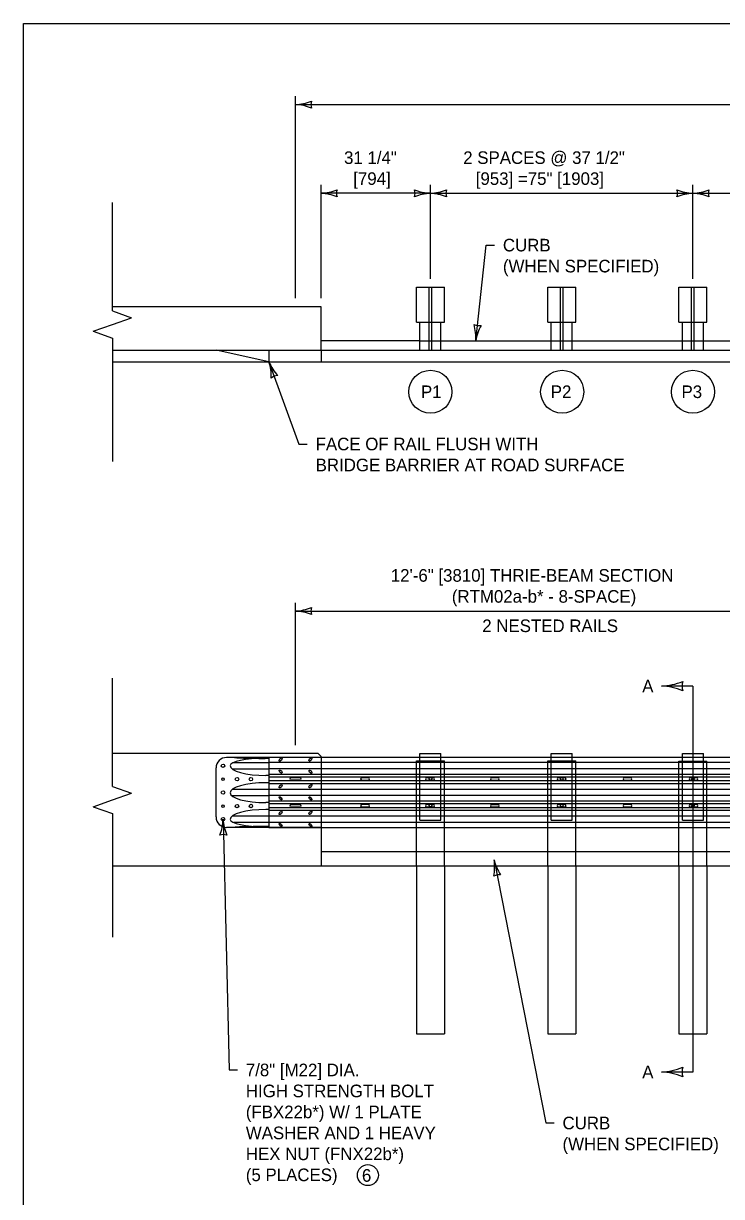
# Model space of a CAD drawing. Extents: x 49991 to 50160, y 49948 to 50051.
# Drawn here: x 49999.38 to 50002.71, y 49993.41 to 49999 of the extents above; entities that cross this region are included whole.
import ezdxf

# ---------------------------------------------------------------- set-up
doc = ezdxf.new("R2010")
doc.units = 0
for name, color, linetype in [('Level 1', 7, 'Continuous'), ('Level 2', 7, 'Continuous'), ('Level 3', 7, 'Continuous'), ('Level 4', 7, 'Continuous'), ('Level 6', 7, 'Continuous')]:
    doc.layers.add(name, color=color, linetype=linetype)

msp = doc.modelspace()

# ---------------------------------------------------------------- linework, layer by layer
at = {"layer": 'Level 1'}
for p, q in [((50001.255, 49997.5765), (50001.255, 49997.7432)), ((50001.255, 49997.7432), (50001.3883, 49997.7432)), ((50001.3883, 49997.5765), (50001.3883, 49997.7432)), ((50001.88, 49997.5765), (50001.88, 49997.7431)), ((50001.88, 49997.7431), (50002.0133, 49997.7431)), ((50002.0133, 49997.5765), (50002.0133, 49997.7431)), ((50002.505, 49997.5765), (50002.505, 49997.7431)), ((50002.505, 49997.7431), (50002.6383, 49997.7431)), ((50002.6383, 49997.5765), (50002.6383, 49997.7431)), ((50001.255, 49997.5765), (50001.3883, 49997.5765)), ((50001.2716, 49997.4432), (50001.2716, 49997.5765)), ((50001.2716, 49997.5765), (50001.3716, 49997.5765)), ((50001.3716, 49997.4432), (50001.3716, 49997.5765)), ((50001.88, 49997.5765), (50002.0133, 49997.5765)), ((50001.8966, 49997.4431), (50001.8966, 49997.5765)), ((50001.8966, 49997.5765), (50001.9966, 49997.5765)), ((50001.9966, 49997.4431), (50001.9966, 49997.5765)), ((50002.505, 49997.5765), (50002.6383, 49997.5765)), ((50002.5216, 49997.4431), (50002.5216, 49997.5765)), ((50002.5216, 49997.5765), (50002.6216, 49997.5765)), ((50002.6216, 49997.4431), (50002.6216, 49997.5765)), ((49999.8072, 49997.4432), (50011.6716, 49997.4427)), ((50000.5527, 49997.387), (50000.3008, 49997.4432)), ((50000.5527, 49997.4432), (50000.5527, 49997.387)), ((50001.2716, 49997.487), (50000.8008, 49997.487)), ((50001.2716, 49997.4432), (50001.3716, 49997.4432)), ((50001.3716, 49997.487), (50001.8966, 49997.4869)), ((50001.8966, 49997.4431), (50001.9966, 49997.4431)), ((50001.9966, 49997.4869), (50002.5216, 49997.4869)), ((50002.5216, 49997.4431), (50002.6216, 49997.4431)), ((50002.6216, 49997.4869), (50002.8341, 49997.4869)), ((49999.8072, 49997.387), (50011.6716, 49997.3865)), ((50000.7868, 49995.5206), (49999.8072, 49995.5206)), ((50000.8008, 49995.5019), (50000.3508, 49995.5019)), ((50000.5527, 49995.4977), (50000.5341, 49995.4977)), ((50004.3866, 49995.5019), (50000.5527, 49995.5019)), ((50000.5527, 49995.5019), (50000.5527, 49995.1685)), ((50000.7868, 49995.5206), (50000.8008, 49995.5066)), ((50000.8008, 49995.5019), (50000.8008, 49995.5066)), ((50001.2716, 49995.5206), (50001.3716, 49995.5206)), ((50001.2716, 49995.5019), (50001.2716, 49995.5206)), ((50001.3716, 49995.5019), (50001.3716, 49995.5206)), ((50001.8966, 49995.5206), (50001.9966, 49995.5206)), ((50001.8966, 49995.5018), (50001.8966, 49995.5206)), ((50001.9966, 49995.5018), (50001.9966, 49995.5206)), ((50002.5216, 49995.5206), (50002.6216, 49995.5206)), ((50002.5216, 49995.5018), (50002.5216, 49995.5206)), ((50002.6216, 49995.5018), (50002.6216, 49995.5206)), ((50000.3008, 49995.2188), (50000.3008, 49995.4519)), ((50000.5527, 49995.4763), (50000.3797, 49995.4763)), ((50000.5527, 49995.4456), (50000.38, 49995.4456)), ((50004.5497, 49995.4776), (50000.5527, 49995.4776)), ((50004.5497, 49995.4485), (50000.5527, 49995.4484)), ((50000.5527, 49995.4165), (50000.5383, 49995.4165)), ((50000.5527, 49995.3813), (50000.5383, 49995.3813)), ((50004.5497, 49995.4214), (50000.5527, 49995.4214)), ((50003.4109, 49995.4083), (50000.5527, 49995.4083)), ((50003.4095, 49995.3899), (50000.5527, 49995.3899)), ((50004.5499, 49995.3768), (50000.5527, 49995.3768)), ((50000.6998, 49995.4056), (50000.6581, 49995.4056)), ((50000.6998, 49995.4056), (50000.6581, 49995.4056)), ((50000.6998, 49995.4056), (50000.6581, 49995.4056)), ((50000.6998, 49995.4056), (50000.6581, 49995.4056)), ((50000.6998, 49995.4056), (50000.6581, 49995.4056)), ((50000.6998, 49995.3931), (50000.6581, 49995.3931)), ((50000.6998, 49995.3931), (50000.6581, 49995.3931)), ((50000.6998, 49995.3931), (50000.6581, 49995.3931)), ((50000.6998, 49995.3931), (50000.6581, 49995.3931)), ((50000.6998, 49995.3931), (50000.6581, 49995.3931)), ((50000.9957, 49995.406), (50001.0252, 49995.406)), ((50001.0252, 49995.3929), (50000.9957, 49995.3929)), ((50001.3046, 49995.406), (50001.3341, 49995.406)), ((50001.3341, 49995.3928), (50001.3046, 49995.3928)), ((50001.6134, 49995.4059), (50001.643, 49995.4059)), ((50001.643, 49995.3928), (50001.6134, 49995.3928)), ((50001.9311, 49995.406), (50001.9606, 49995.406)), ((50001.9606, 49995.3928), (50001.9311, 49995.3928)), ((50002.2453, 49995.406), (50002.2748, 49995.406)), ((50002.2748, 49995.3928), (50002.2453, 49995.3928)), ((50002.5595, 49995.406), (50002.589, 49995.406)), ((50002.589, 49995.3928), (50002.5595, 49995.3928)), ((50000.5527, 49995.3189), (50000.3766, 49995.3189)), ((50000.5527, 49995.3496), (50000.3768, 49995.3496)), ((50004.5505, 49995.3498), (50000.5527, 49995.3498)), ((50004.5497, 49995.3206), (50000.5527, 49995.3206)), ((50000.5527, 49995.2872), (50000.5383, 49995.2872)), ((50004.5497, 49995.2936), (50000.5527, 49995.2936)), ((50003.4116, 49995.2805), (50000.5527, 49995.2805)), ((50003.4083, 49995.2621), (50000.5527, 49995.2621)), ((50000.6998, 49995.2769), (50000.6581, 49995.2769)), ((50000.6998, 49995.2769), (50000.6581, 49995.2769)), ((50000.6998, 49995.2769), (50000.6581, 49995.2769)), ((50000.6998, 49995.2769), (50000.6581, 49995.2769)), ((50000.6998, 49995.2769), (50000.6581, 49995.2769)), ((50000.6998, 49995.2644), (50000.6581, 49995.2644)), ((50000.6998, 49995.2644), (50000.6581, 49995.2644)), ((50000.6998, 49995.2644), (50000.6581, 49995.2644)), ((50000.6998, 49995.2644), (50000.6581, 49995.2644)), ((50000.6998, 49995.2644), (50000.6581, 49995.2644)), ((50000.9957, 49995.2787), (50001.0252, 49995.2787)), ((50001.0252, 49995.2656), (50000.9957, 49995.2656)), ((50001.3046, 49995.2787), (50001.3341, 49995.2787)), ((50001.3341, 49995.2655), (50001.3046, 49995.2655)), ((50001.6134, 49995.2786), (50001.643, 49995.2786)), ((50001.643, 49995.2655), (50001.6134, 49995.2655)), ((50001.9311, 49995.2787), (50001.9606, 49995.2787)), ((50001.9606, 49995.2655), (50001.9311, 49995.2655)), ((50002.2453, 49995.2787), (50002.2748, 49995.2787)), ((50002.2748, 49995.2655), (50002.2453, 49995.2655)), ((50002.5595, 49995.2787), (50002.589, 49995.2787)), ((50002.589, 49995.2655), (50002.5595, 49995.2655)), ((50000.5527, 49995.2223), (50000.3767, 49995.2223)), ((50000.5527, 49995.2542), (50000.5383, 49995.2542)), ((50004.5497, 49995.249), (50000.5527, 49995.249)), ((50004.5497, 49995.222), (50000.5527, 49995.222)), ((50000.8008, 49995.1685), (50000.3508, 49995.1685)), ((50000.8008, 49995.1685), (50000.3508, 49995.1685)), ((50000.5527, 49995.1917), (50000.3851, 49995.1917)), ((50000.5527, 49995.1917), (50000.3851, 49995.1917)), ((50000.5527, 49995.1727), (50000.5341, 49995.1727)), ((50004.5497, 49995.1928), (50000.5527, 49995.1928)), ((50000.5527, 49995.1685), (50004.5497, 49995.1685)), ((50000.8008, 49995.1685), (50000.8008, 49994.9852)), ((50001.255, 49995.0519), (50001.255, 49995.1685)), ((50001.3883, 49995.0519), (50001.3883, 49995.1685)), ((50001.88, 49995.0518), (50001.88, 49995.1685)), ((50002.0133, 49995.0518), (50002.0133, 49995.1685)), ((50002.505, 49995.0518), (50002.505, 49995.1685)), ((50002.6383, 49995.0518), (50002.6383, 49995.1685)), ((50011.6716, 49995.0514), (50000.8008, 49995.0519)), ((49999.8072, 49994.9853), (50011.6716, 49994.9848))]:
    msp.add_line(p, q, dxfattribs=at)
msp.add_lwpolyline([(49999.3835, 49998.9992), (50016.7501, 49998.9992), (50016.7501, 49987.7988), (49999.3835, 49987.7988)], close=True, dxfattribs=at)
msp.add_lwpolyline([(50000.8008, 49997.4432), (50000.8008, 49997.6496), (49999.8072, 49997.6496)], dxfattribs=at)
for centre, radius in [((50000.3337, 49995.4625), 0.00833), ((50000.3337, 49995.3985), 0.00625), ((50000.4004, 49995.3985), 0.00833), ((50000.4004, 49995.3985), 0.00833), ((50000.4004, 49995.3985), 0.00833), ((50000.4004, 49995.3985), 0.00833), ((50000.4004, 49995.3985), 0.00833), ((50000.4666, 49995.3989), 0.00833), ((50000.4666, 49995.3989), 0.00833), ((50000.4666, 49995.3989), 0.00833), ((50000.4666, 49995.3989), 0.00833), ((50000.4666, 49995.3989), 0.00833), ((50001.3216, 49995.3998), 0.00625), ((50001.9466, 49995.3998), 0.00625), ((50002.5716, 49995.3997), 0.00625), ((50000.3337, 49995.3352), 0.00833), ((50000.3337, 49995.2703), 0.00625), ((50000.4004, 49995.2703), 0.00833), ((50000.4004, 49995.2703), 0.00833), ((50000.4004, 49995.2703), 0.00833), ((50000.4004, 49995.2703), 0.00833), ((50000.4004, 49995.2703), 0.00833), ((50000.4666, 49995.2707), 0.00833), ((50000.4666, 49995.2707), 0.00833), ((50000.4666, 49995.2707), 0.00833), ((50000.4666, 49995.2707), 0.00833), ((50000.4666, 49995.2707), 0.00833), ((50001.3216, 49995.2727), 0.00625), ((50001.9466, 49995.2727), 0.00625), ((50002.5716, 49995.2727), 0.00625), ((50000.3337, 49995.2079), 0.00833)]:
    msp.add_circle(centre, radius, dxfattribs=at)
for centre, radius, start, end in [((50000.3508, 49995.4519), 0.05, 90, 180), ((50000.6581, 49995.3993), 0.00625, 90, 270), ((50000.6581, 49995.3993), 0.00625, 90, 270), ((50000.6581, 49995.3993), 0.00625, 90, 270), ((50000.6581, 49995.3993), 0.00625, 90, 270), ((50000.6581, 49995.3993), 0.00625, 90, 270), ((50000.6998, 49995.3993), 0.00625, 270, 90), ((50000.6998, 49995.3993), 0.00625, 270, 90), ((50000.6998, 49995.3993), 0.00625, 270, 90), ((50000.6998, 49995.3993), 0.00625, 270, 90), ((50000.6998, 49995.3993), 0.00625, 270, 90), ((50000.9957, 49995.3994), 0.00656, 90, 270), ((50001.0252, 49995.3994), 0.00656, 270, 90), ((50001.3046, 49995.3994), 0.00656, 90, 270), ((50001.3341, 49995.3994), 0.00656, 270, 90), ((50001.6134, 49995.3994), 0.00656, 90, 270), ((50001.643, 49995.3994), 0.00656, 270, 90), ((50001.9311, 49995.3994), 0.00656, 90, 270), ((50001.9606, 49995.3994), 0.00656, 270, 90), ((50002.2453, 49995.3994), 0.00656, 90, 270), ((50002.2748, 49995.3994), 0.00656, 270, 90), ((50002.5595, 49995.3994), 0.00656, 90, 270), ((50002.589, 49995.3994), 0.00656, 270, 90), ((50000.6581, 49995.2707), 0.00625, 90, 270), ((50000.6581, 49995.2707), 0.00625, 90, 270), ((50000.6581, 49995.2707), 0.00625, 90, 270), ((50000.6581, 49995.2707), 0.00625, 90, 270), ((50000.6581, 49995.2707), 0.00625, 90, 270), ((50000.6998, 49995.2707), 0.00625, 270, 90), ((50000.6998, 49995.2707), 0.00625, 270, 90), ((50000.6998, 49995.2707), 0.00625, 270, 90), ((50000.6998, 49995.2707), 0.00625, 270, 90), ((50000.6998, 49995.2707), 0.00625, 270, 90), ((50000.9957, 49995.2721), 0.00656, 90, 270), ((50001.0252, 49995.2721), 0.00656, 270, 90), ((50001.3046, 49995.2721), 0.00656, 90, 270), ((50001.3341, 49995.2721), 0.00656, 270, 90), ((50001.6134, 49995.2721), 0.00656, 90, 270), ((50001.643, 49995.2721), 0.00656, 270, 90), ((50001.9311, 49995.2721), 0.00656, 90, 270), ((50001.9606, 49995.2721), 0.00656, 270, 90), ((50002.2453, 49995.2721), 0.00656, 90, 270), ((50002.2748, 49995.2721), 0.00656, 270, 90), ((50002.5595, 49995.2721), 0.00656, 90, 270), ((50002.589, 49995.2721), 0.00656, 270, 90), ((50000.3508, 49995.2185), 0.05, 180, 270)]:
    msp.add_arc(centre, radius, start, end, dxfattribs=at)
for centre, major_axis, ratio, start_param, end_param in [((50000.5341, 49995.4633), (-0.1667, 0), 0.2062, 4.712389, 6.283185), ((50000.5341, 49995.4633), (-0.1667, 0), 0.2062, 4.712389, 6.283185), ((50000.5341, 49995.4633), (-0.1667, 0), 0.2062, 4.712389, 6.283185), ((50000.5341, 49995.4633), (-0.1667, 0), 0.2062, 4.712389, 6.283185), ((50000.5341, 49995.4633), (-0.1667, 0), 0.2062, 4.712389, 6.283185), ((50000.5341, 49995.5019), (-0.1461, 0), 0.028516, 0, 1.570796), ((50000.5341, 49995.5019), (-0.1461, 0), 0.028516, 0, 1.570796), ((50000.5341, 49995.5019), (-0.1461, 0), 0.028516, 0, 1.570796), ((50000.5341, 49995.5019), (-0.1461, 0), 0.028516, 0, 1.570796), ((50000.5341, 49995.5019), (-0.1461, 0), 0.028516, 0, 1.570796), ((50000.5383, 49995.4633), (-0.1708, 0), 0.27561, 0, 1.570796), ((50000.5383, 49995.4633), (-0.1708, 0), 0.27561, 0, 1.570796), ((50000.5383, 49995.4633), (-0.1708, 0), 0.27561, 0, 1.570796), ((50000.5383, 49995.4633), (-0.1708, 0), 0.27561, 0, 1.570796), ((50000.5383, 49995.4633), (-0.1708, 0), 0.27561, 0, 1.570796), ((50000.5383, 49995.3342), (-0.1708, 0), 0.27561, 4.712389, 6.283185), ((50000.5383, 49995.3342), (-0.1708, 0), 0.27561, 4.712389, 6.283185), ((50000.5383, 49995.3342), (-0.1708, 0), 0.27561, 4.712389, 6.283185), ((50000.5383, 49995.3342), (-0.1708, 0), 0.27561, 4.712389, 6.283185), ((50000.5383, 49995.3342), (-0.1708, 0), 0.27561, 4.712389, 6.283185), ((50000.5383, 49995.3341), (-0.1708, 0), 0.27561, 0, 1.570796), ((50000.5383, 49995.3341), (-0.1708, 0), 0.27561, 0, 1.570796), ((50000.5383, 49995.3341), (-0.1708, 0), 0.27561, 0, 1.570796), ((50000.5383, 49995.3341), (-0.1708, 0), 0.27561, 0, 1.570796), ((50000.5383, 49995.3341), (-0.1708, 0), 0.27561, 0, 1.570796), ((50000.5383, 49995.2071), (-0.1708, 0), 0.27561, 4.712389, 6.283185), ((50000.5383, 49995.2071), (-0.1708, 0), 0.27561, 4.712389, 6.283185), ((50000.5383, 49995.2071), (-0.1708, 0), 0.27561, 4.712389, 6.283185), ((50000.5383, 49995.2071), (-0.1708, 0), 0.27561, 4.712389, 6.283185), ((50000.5383, 49995.2071), (-0.1708, 0), 0.27561, 4.712389, 6.283185), ((50000.5341, 49995.2071), (-0.1667, 0), 0.2062, 0, 1.570796), ((50000.5341, 49995.2071), (-0.1667, 0), 0.2062, 0, 1.570796), ((50000.5341, 49995.2071), (-0.1667, 0), 0.2062, 0, 1.570796), ((50000.5341, 49995.2071), (-0.1667, 0), 0.2062, 0, 1.570796), ((50000.5341, 49995.2071), (-0.1667, 0), 0.2062, 0, 1.570796), ((50000.5341, 49995.1685), (-0.1461, 0), 0.028516, 4.712389, 6.283185), ((50000.5341, 49995.1685), (-0.1461, 0), 0.028516, 4.712389, 6.283185), ((50000.5341, 49995.1685), (-0.1461, 0), 0.028516, 4.712389, 6.283185), ((50000.5341, 49995.1685), (-0.1461, 0), 0.028516, 4.712389, 6.283185), ((50000.5341, 49995.1685), (-0.1461, 0), 0.028516, 4.712389, 6.283185)]:
    msp.add_ellipse(centre, major_axis=major_axis, ratio=ratio, start_param=start_param, end_param=end_param, dxfattribs=at)
for centre, major_axis in [((50000.6082, 49995.4922), (-0.00633, -0.00754)), ((50000.7497, 49995.4922), (-0.00633, -0.00754)), ((50000.6082, 49995.4347), (-0.00633, 0.00754)), ((50000.7497, 49995.4347), (-0.00633, 0.00754)), ((50000.6082, 49995.3649), (-0.00633, -0.00754)), ((50000.7497, 49995.3649), (-0.00633, -0.00754)), ((50000.6082, 49995.3074), (-0.00633, 0.00754)), ((50000.7497, 49995.3074), (-0.00633, 0.00754)), ((50000.6082, 49995.2378), (-0.00633, -0.00754)), ((50000.7497, 49995.2378), (-0.00633, -0.00754)), ((50000.6082, 49995.1803), (-0.00633, 0.00754)), ((50000.7497, 49995.1803), (-0.00633, 0.00754))]:
    msp.add_ellipse(centre, major_axis=major_axis, ratio=0.447911, dxfattribs=at)
at = {"layer": 'Level 2'}
for centre, radius in [((50001.3215, 49997.2443), 0.1026), ((50001.949, 49997.2443), 0.1026), ((50002.5716, 49997.2443), 0.1026), ((50001.0235, 49993.512), 0.05)]:
    msp.add_circle(centre, radius, dxfattribs=at)
at = {"layer": 'Level 3'}
for p, q in [((50000.679, 49997.6896), (50000.679, 49998.6527)), ((50000.679, 49998.6127), (50008.1966, 49998.6127)), ((50000.8008, 49997.6896), (50000.8008, 49998.2299)), ((50001.3216, 49997.7832), (50001.3216, 49998.2299)), ((50002.5716, 49997.7831), (50002.5716, 49998.2299)), ((50001.3216, 49998.1899), (50000.8008, 49998.1899)), ((50001.3216, 49998.1899), (50002.5716, 49998.1899)), ((50002.5716, 49998.1899), (50003.8216, 49998.1899)), ((50001.5376, 49997.487), (50001.5866, 49997.9431)), ((50001.5866, 49997.9431), (50001.6266, 49997.9431)), ((50000.5527, 49997.387), (50000.6949, 49996.9955)), ((50000.6949, 49996.9955), (50000.7349, 49996.9955)), ((50000.679, 49995.5606), (50000.679, 49996.2394)), ((50000.679, 49996.1994), (50003.1966, 49996.1994)), ((50000.3337, 49995.2079), (50000.3624, 49994.0131)), ((50001.6247, 49995.0141), (50001.8705, 49993.7604)), ((50000.3624, 49994.0131), (50000.4024, 49994.0131)), ((50001.8705, 49993.7604), (50001.9105, 49993.7604))]:
    msp.add_line(p, q, dxfattribs=at)
for centre, radius, start, end in [((50000.6675, 49998.8454), 0.233, 272.8273, 292.0772), ((50000.8072, 49998.6127), 0.0548, 162.1388, 197.8612), ((50000.6699, 49998.3905), 0.2223, 67.456, 87.6395), ((50000.7893, 49998.4226), 0.233, 272.8273, 292.0772), ((50000.7917, 49997.9678), 0.2223, 67.456, 87.6395), ((50000.929, 49998.1899), 0.0548, 162.1388, 197.8612), ((50001.3308, 49998.412), 0.2223, 247.456, 267.6395), ((50001.1934, 49998.1899), 0.0548, 342.1388, 17.8612), ((50001.3331, 49997.9572), 0.233, 92.8273, 112.0772), ((50001.3102, 49998.4226), 0.233, 272.8273, 292.0772), ((50001.3125, 49997.9678), 0.2223, 67.456, 87.6395), ((50001.4499, 49998.1899), 0.0548, 162.1388, 197.8612), ((50002.5808, 49998.412), 0.2223, 247.456, 267.6395), ((50002.4434, 49998.1899), 0.0548, 342.1388, 17.8612), ((50002.5831, 49997.9572), 0.233, 92.8273, 112.0772), ((50002.5602, 49998.4226), 0.233, 272.8273, 292.0772), ((50002.5625, 49997.9678), 0.2223, 67.456, 87.6395), ((50002.6999, 49998.1899), 0.0548, 162.1388, 197.8612), ((50001.5513, 49997.6144), 0.0548, 246.0178, 281.7402), ((50001.305, 49997.5003), 0.233, 356.7063, 15.9562), ((50001.7575, 49997.4542), 0.2223, 151.335, 171.5185), ((50000.3408, 49997.3197), 0.2223, 357.4214, 17.6049), ((50000.7675, 49997.4772), 0.233, 202.7927, 222.0426), ((50000.5965, 49997.2665), 0.0548, 92.1042, 127.8266), ((50000.6675, 49996.4322), 0.233, 272.8273, 292.0772), ((50000.8072, 49996.1994), 0.0548, 162.1388, 197.8612), ((50000.6698, 49995.9773), 0.2223, 67.456, 87.6395), ((50002.4063, 49996.1523), 0.3107, 272.8273, 292.0772), ((50002.4094, 49995.5459), 0.2964, 67.456, 87.6395), ((50002.5926, 49995.842), 0.073, 162.1388, 197.8612), ((50000.1114, 49995.2117), 0.2223, 338.834, 359.0175), ((50000.5661, 49995.225), 0.233, 184.2053, 203.4551), ((50000.3368, 49995.0797), 0.0548, 73.5168, 109.2391), ((50001.4049, 49994.9803), 0.2223, 348.5492, 8.7327), ((50001.8508, 49995.0701), 0.233, 193.9205, 213.1704), ((50001.6494, 49994.8882), 0.0548, 83.232, 118.9544), ((50002.4063, 49994.3136), 0.3107, 272.8273, 292.0772), ((50002.4094, 49993.7071), 0.2964, 67.456, 87.6395), ((50002.5926, 49994.0033), 0.073, 162.1388, 197.8612)]:
    msp.add_arc(centre, radius, start, end, dxfattribs=at)
at = {"layer": 'Level 4'}
for p, q in [((50001.3154, 49997.5765), (50001.3154, 49997.7432)), ((50001.3279, 49997.5765), (50001.3279, 49997.7432)), ((50001.9404, 49997.5765), (50001.9404, 49997.7431)), ((50001.9529, 49997.5765), (50001.9529, 49997.7431)), ((50002.5654, 49997.5765), (50002.5654, 49997.7431)), ((50002.5779, 49997.5765), (50002.5779, 49997.7431)), ((50001.3154, 49997.4432), (50001.3154, 49997.5765)), ((50001.3279, 49997.4432), (50001.3279, 49997.5765)), ((50001.9404, 49997.4431), (50001.9404, 49997.5765)), ((50001.9529, 49997.4431), (50001.9529, 49997.5765)), ((50002.5654, 49997.4431), (50002.5654, 49997.5765)), ((50002.5779, 49997.4431), (50002.5779, 49997.5765)), ((50000.8008, 49997.4432), (50000.8008, 49997.387)), ((50001.2716, 49997.487), (50001.3716, 49997.487)), ((50001.8966, 49997.4869), (50001.9966, 49997.4869)), ((50002.5216, 49997.4869), (50002.6216, 49997.4869)), ((50000.8008, 49995.5019), (50000.8008, 49995.1685)), ((50001.2716, 49995.204), (50001.2716, 49995.5019)), ((50001.3716, 49995.204), (50001.3716, 49995.5019)), ((50001.8966, 49995.2039), (50001.8966, 49995.5018)), ((50001.9966, 49995.2039), (50001.9966, 49995.5018)), ((50002.5216, 49995.2039), (50002.5216, 49995.5018)), ((50002.6216, 49995.2039), (50002.6216, 49995.5018)), ((50001.255, 49995.1685), (50001.255, 49995.4852)), ((50001.255, 49995.4852), (50001.3883, 49995.4852)), ((50001.3883, 49995.1685), (50001.3883, 49995.4852)), ((50001.88, 49995.1685), (50001.88, 49995.4852)), ((50001.88, 49995.4852), (50002.0133, 49995.4852)), ((50002.0133, 49995.1686), (50002.0133, 49995.4852)), ((50002.505, 49995.1685), (50002.505, 49995.4851)), ((50002.505, 49995.4851), (50002.6383, 49995.4851)), ((50002.6383, 49995.1686), (50002.6383, 49995.4851)), ((50001.2716, 49995.204), (50001.3716, 49995.204)), ((50001.8966, 49995.2039), (50001.9966, 49995.2039)), ((50002.5216, 49995.2039), (50002.6216, 49995.2039)), ((50001.255, 49994.9852), (50001.255, 49995.0519)), ((50001.3883, 49994.9852), (50001.3883, 49995.0519)), ((50001.88, 49994.9852), (50001.88, 49995.0518)), ((50002.0133, 49994.9852), (50002.0133, 49995.0518)), ((50002.505, 49994.9851), (50002.505, 49995.0518)), ((50002.6383, 49994.9851), (50002.6383, 49995.0518)), ((50001.255, 49994.9852), (50001.255, 49994.1852)), ((50001.3883, 49994.9852), (50001.3883, 49994.1852)), ((50001.88, 49994.9852), (50001.88, 49994.1852)), ((50002.0133, 49994.9852), (50002.0133, 49994.1852)), ((50002.505, 49994.9851), (50002.505, 49994.1851)), ((50002.6383, 49994.9851), (50002.6383, 49994.1851)), ((50001.255, 49994.1852), (50001.3883, 49994.1852)), ((50001.88, 49994.1852), (50002.0133, 49994.1852)), ((50002.505, 49994.1851), (50002.6383, 49994.1851))]:
    msp.add_line(p, q, dxfattribs=at)
at = {"layer": 'Level 6'}
for p, q in [((49999.8072, 49997.6297), (49999.8072, 49998.1459)), ((49999.8072, 49997.6297), (49999.8986, 49997.5973)), ((49999.7158, 49997.5325), (49999.8072, 49997.5649)), ((49999.8072, 49997.5649), (49999.8986, 49997.5973)), ((49999.7158, 49997.5325), (49999.8072, 49997.5001)), ((49999.8072, 49997.5001), (49999.8072, 49996.9118)), ((49999.8072, 49995.3643), (49999.8072, 49995.8805)), ((50002.5716, 49995.842), (50002.4216, 49995.842)), ((50002.5716, 49995.842), (50002.5716, 49994.0033)), ((49999.8072, 49995.3643), (49999.8986, 49995.3319)), ((49999.8072, 49995.2995), (49999.8986, 49995.3319)), ((49999.7158, 49995.2671), (49999.8072, 49995.2995)), ((49999.7158, 49995.2671), (49999.8072, 49995.2347)), ((49999.8072, 49995.2347), (49999.8072, 49994.6464)), ((50002.5716, 49994.0033), (50002.4216, 49994.0033))]:
    msp.add_line(p, q, dxfattribs=at)

# ---------------------------------------------------------------- texts
at = {"layer": 'Level 2'}
for s, p in [('31 1/4"', (50000.9102, 49998.3299)), ('2 SPACES @ 37 1/2" ', (50001.4777, 49998.3299)), ('[794]', (50000.954, 49998.2299)), ('[953] =75" [1903]', (50001.5374, 49998.2299)), ('CURB', (50001.6666, 49997.9131)), ('(WHEN SPECIFIED)', (50001.6666, 49997.8131)), ('P1', (50001.2764, 49997.2143)), ('P2', (50001.8946, 49997.2145)), ('P3', (50002.5172, 49997.2144)), ('FACE OF RAIL FLUSH WITH', (50000.7749, 49996.9655)), ('BRIDGE BARRIER AT ROAD SURFACE', (50000.7749, 49996.8655)), ('12\'-6" [3810] THRIE-BEAM SECTION', (50001.1328, 49996.3394)), (' (RTM02a-b* - 8-SPACE)', (50001.4011, 49996.2394)), ('2 NESTED RAILS', (50001.5683, 49996.0994)), ('A', (50002.3301, 49995.812)), ('7/8" [M22] DIA. ', (50000.4424, 49993.9831)), ('A', (50002.3301, 49993.9733)), ('HIGH STRENGTH BOLT ', (50000.4424, 49993.8832)), ('(FBX22b*) W/ 1 PLATE', (50000.4424, 49993.7832)), ('CURB', (50001.9505, 49993.7304)), ('WASHER AND 1 HEAVY', (50000.4424, 49993.6832)), ('HEX NUT (FNX22b*) ', (50000.4424, 49993.5833)), ('(WHEN SPECIFIED)', (50001.9505, 49993.6304)), ('(5 PLACES)', (50000.4424, 49993.4833)), ('6', (50000.9953, 49993.4804))]:
    msp.add_text(s, height=0.06, dxfattribs=at).set_placement(p)

doc.saveas('drawing.dxf')
